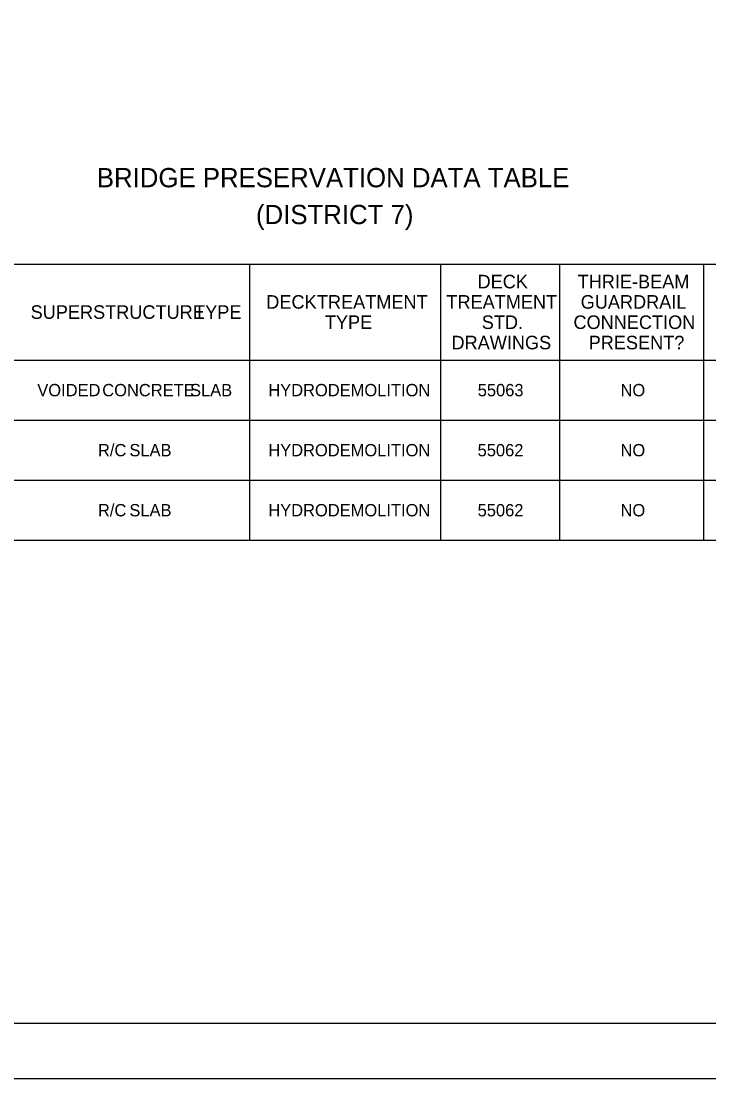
# Model space of a CAD drawing. Extents: x 16 to 1228740, y 11 to 152440.
# Drawn here: x 16.836 to 17.432, y 10.709 to 11.626 of the extents above; entities that cross this region are included whole.
import ezdxf

# ---------------------------------------------------------------- set-up
doc = ezdxf.new("R2010")
doc.units = 0
doc.layers.add('B_Text', color=7, linetype='Continuous')
doc.layers.add('R_Border', color=7, linetype='Continuous')

msp = doc.modelspace()

# ---------------------------------------------------------------- linework, layer by layer
at = {"layer": 'B_Text'}
for p, q in [((16.24888, 11.41567), (17.9766, 11.41567)), ((17.03468, 11.17628), (17.03468, 11.41567)), ((17.20017, 11.17628), (17.20017, 11.41567)), ((17.3032, 11.17628), (17.3032, 11.41567)), ((17.4281, 11.17628), (17.4281, 11.41567)), ((16.24888, 11.3324), (17.9766, 11.3324)), ((16.24888, 11.28036), (17.9766, 11.28036)), ((16.24888, 11.22832), (17.9766, 11.22832)), ((16.24888, 11.17628), (17.9766, 11.17628))]:
    msp.add_line(p, q, dxfattribs=at)
at = {"layer": 'R_Border'}
msp.add_line((18.44221, 10.75755), (15.78327, 10.75755), dxfattribs=at)
msp.add_lwpolyline([(15.65694, 12.54282), (18.49027, 12.54282), (18.49027, 10.70949), (15.65694, 10.70949)], close=True, dxfattribs=at)

# ---------------------------------------------------------------- texts
at = {"layer": 'B_Text'}
for s, p in [('BRIDGE PRESERVATION DATA TABLE ', (16.902, 11.48218)), ('(DISTRICT 7)', (17.03992, 11.45023))]:
    msp.add_text(s, height=0.0167, rotation=360, dxfattribs=at).set_placement(p)
for s, height, p in [('DECK', 0.011742, (17.23195, 11.39458)), ('THRIE-BEAM', 0.011742, (17.31864, 11.39458)), ('DECK', 0.011742, (17.04886, 11.37697)), (' TREATMENT', 0.011742, (17.08832, 11.37697)), ('TREATMENT', 0.011742, (17.20494, 11.37697)), ('GUARDRAIL', 0.011742, (17.3213, 11.37697)), ('SUPERSTRUCTURE', 0.0117423, (16.84463, 11.36816)), (' TYPE', 0.011742, (16.98194, 11.36816)), ('TYPE', 0.011742, (17.09959, 11.35936)), ('STD.', 0.011742, (17.23558, 11.35936)), ('CONNECTION', 0.011742, (17.31504, 11.35936)), ('DRAWINGS', 0.011742, (17.20934, 11.34174)), ('PRESENT?', 0.011742, (17.32822, 11.34174)), ('VOIDED', 0.010675, (16.85041, 11.30105)), (' CONCRETE', 0.010675, (16.90273, 11.30105)), (' SLAB', 0.010675, (16.97881, 11.30105)), ('HYDRODEMOLITION', 0.0106748, (17.05059, 11.30105)), ('55063', 0.010675, (17.23207, 11.30105)), ('NO', 0.010675, (17.35579, 11.30105)), ('R/C', 0.010675, (16.90296, 11.24901)), (' SLAB', 0.010675, (16.92626, 11.24901)), ('HYDRODEMOLITION', 0.0106748, (17.05059, 11.24901)), ('55062', 0.010675, (17.23198, 11.24901)), ('NO', 0.010675, (17.35579, 11.24901)), ('R/C', 0.010675, (16.90296, 11.19697)), (' SLAB', 0.010675, (16.92626, 11.19697)), ('HYDRODEMOLITION', 0.0106748, (17.05059, 11.19697)), ('55062', 0.010675, (17.23198, 11.19697)), ('NO', 0.010675, (17.35579, 11.19697))]:
    msp.add_text(s, height=height, dxfattribs=at).set_placement(p)

doc.saveas('drawing.dxf')
